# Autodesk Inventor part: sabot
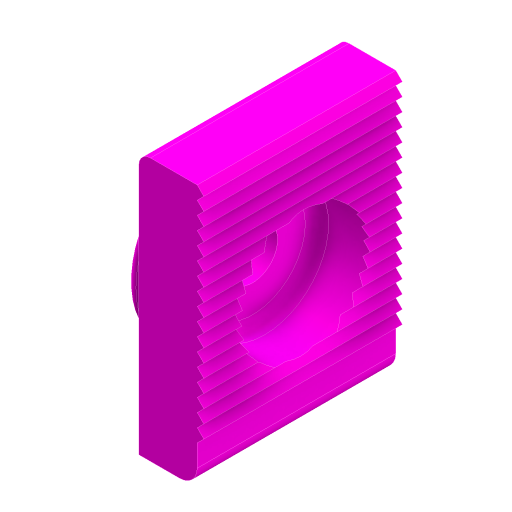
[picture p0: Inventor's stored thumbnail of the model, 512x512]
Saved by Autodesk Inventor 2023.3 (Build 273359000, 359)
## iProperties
Created: 2024-11
Part Number: sabot
Material: Générique
Description: STEP AP203
Document SubType Name: Modeling
Designer: Thier
Density: 1 g/cm^3
Appearance: Magenta
Sending System: SolidWorks 2017
Preprocessor: SwSTEP 2.0
Title: sabot.STEP
Revision Number: ANY
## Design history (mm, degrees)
feature "Enlèv. mat.-Extru.15"
node "Solide1"
